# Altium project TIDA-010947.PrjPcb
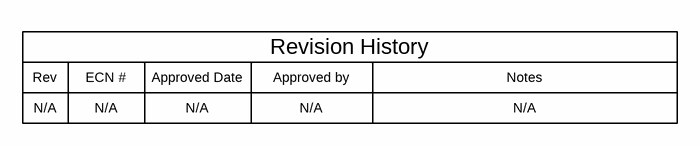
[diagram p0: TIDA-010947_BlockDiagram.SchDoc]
CopyrightYear: 2024; PCB_Layout: Who did the Layout?; PCB_Rev: E1.2; PRJ_Customer: Public Release; PRJ_Engineer: Enter name of project lead; PRJ_Number: TIDA-010947; PRJ_Title: Change in menu Project|Project Options|Parameters; SCH_Rev: E1.2; TechSupport: http://www.ti.com/support; TID: N/A
3 sheets, 68 parts. Net scope: flat (ports and power ports of the same name join across sheets).
Board file: TIDA-010947_PCB_E1.2.PcbDoc
Sheets:
  TIDA-010947_BlockDiagram.SchDoc
  TIDA-010947_Schematic.SchDoc
  TIDA-010947_Hardware.SchDoc

## Sheet TIDA-010947_BlockDiagram.SchDoc
size 431 x 279 mm; Date: Not shown in title block; ApprovedBy: Not shown in title block; CheckedBy: Not shown in title block; Author: Not shown in title block; CompanyName: Not shown in title block; Engineer: Not shown in title block; Organization: Not shown in title block; Address1: Not shown in title block; Address2: Not shown in title block; Address3: Not shown in title block; Address4: Not shown in title block; DocumentNumber: 1; Revision: Use project parameter SCH_Rev; SheetNumber: 1; SheetTotal: 3; PageSetup: Record=PageOptions¦CenterHorizontal=True¦CenterVertical=True¦PrintScale=1.00¦XCorrection=1.00¦YCorrection=1.00¦PrintKind=0¦BorderSize=5000000¦LeftOffset=0¦BottomOffset=0¦Orientation=2¦PaperLength=1000¦PaperWidth=1000¦Scale=100¦PaperSource=15¦PrintQuality=600¦MediaType=1¦DitherType=10¦PaperKind=Letter¦PrintScaleMode=1

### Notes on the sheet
- Rev
- N/A
- ECN #
- Approved Date
- Approved by
- Revision History
- Notes

## Sheet TIDA-010947_Schematic.SchDoc
size 431 x 279 mm; Date: Not shown in title block; ApprovedBy: Not shown in title block; CheckedBy: Not shown in title block; Author: Not shown in title block; CompanyName: Not shown in title block; Engineer: Not shown in title block; Organization: Not shown in title block; Address1: Not shown in title block; Address2: Not shown in title block; Address3: Not shown in title block; Address4: Not shown in title block; DocumentNumber: 2; Revision: Use project parameter SCH_Rev; SheetNumber: 2; SheetTotal: 3; PageSetup: Record=PageOptions¦CenterHorizontal=True¦CenterVertical=True¦PrintScale=1.00¦XCorrection=1.00¦YCorrection=1.00¦PrintKind=0¦BorderSize=5000000¦LeftOffset=0¦BottomOffset=0¦Orientation=2¦PaperLength=1000¦PaperWidth=1000¦Scale=100¦PaperSource=15¦PrintQuality=600¦MediaType=1¦DitherType=10¦PaperKind=Letter¦PrintScaleMode=1
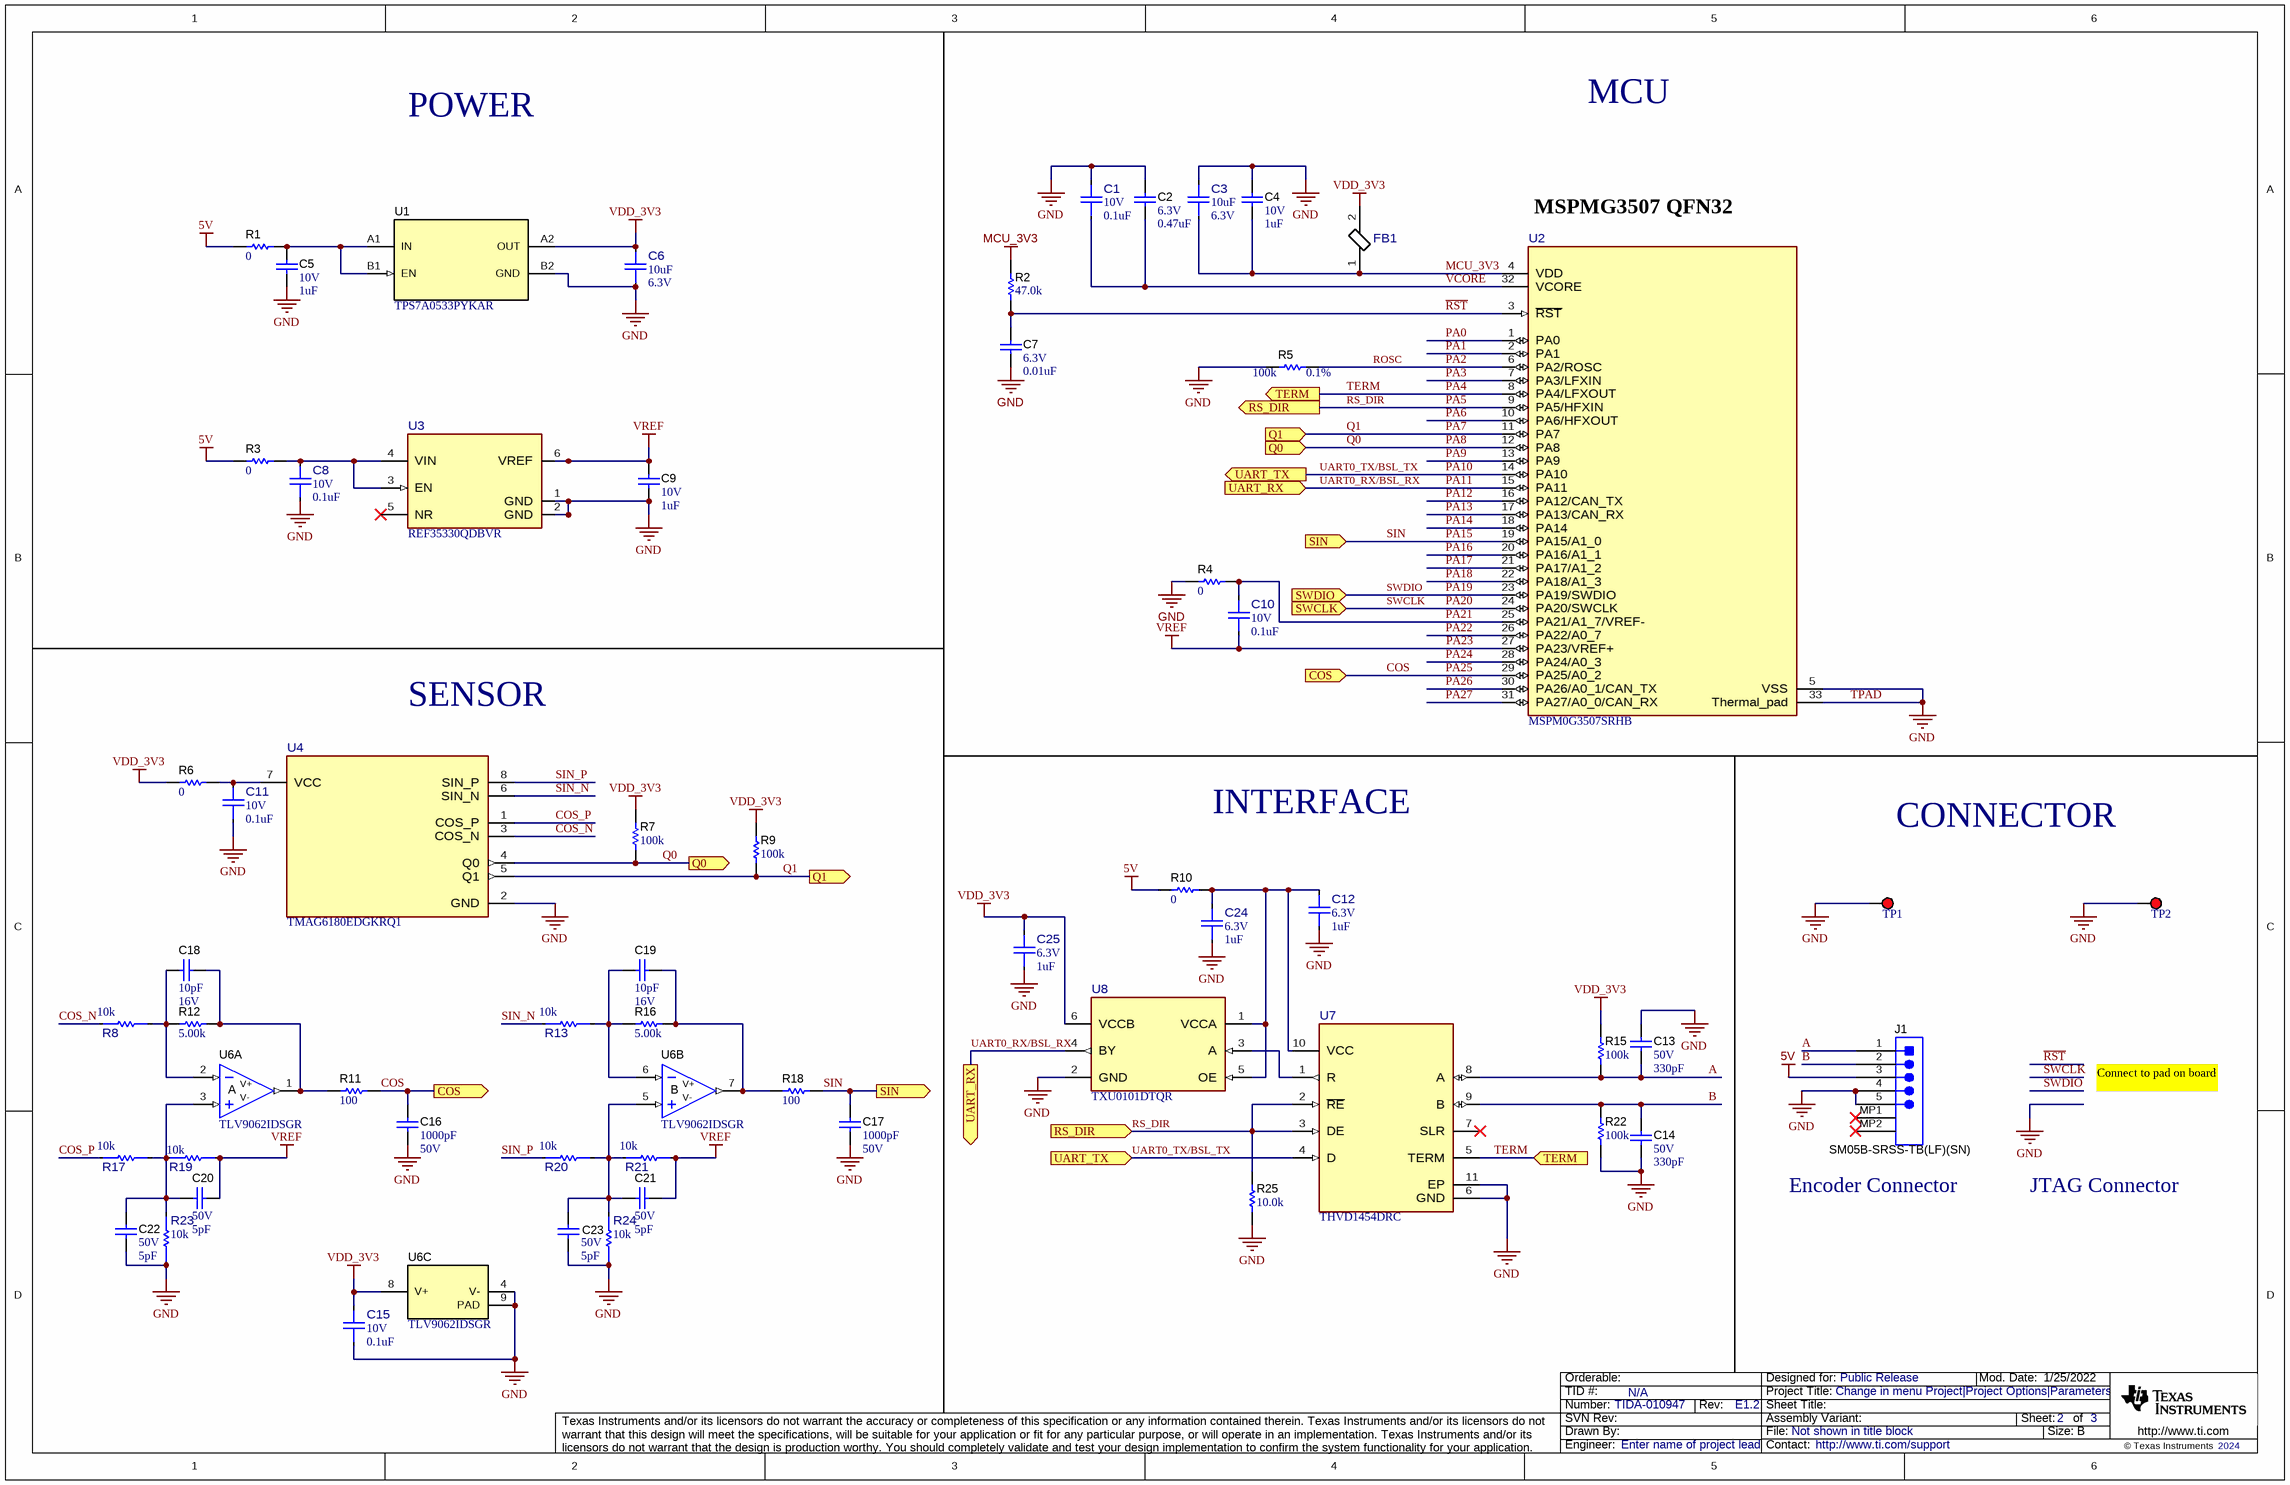
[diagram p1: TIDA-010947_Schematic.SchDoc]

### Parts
C1  VDC_V: 10V  ValueDisplayed: 0.1uF  [FP-LMK063BJ104KP-F_0201-MFG]  (hidden comment: LMK063BJ104KP-F)
C2  VDC_V: 6.3V  ValueDisplayed: 0.47uF  [0201_033]  (hidden comment: CL03A474KQ3NNNC)
C3  ValueDisplayed: 10uF  VDC_V: 6.3V  [FP-ZRB15XC80J106ME05D_0402-MFG]  (hidden comment: ZRB15XC80J106ME05D)
C4  VDC_V: 10V  ValueDisplayed: 1uF  [0201]  (hidden comment: CL03A105MP3NSNC)
C5  VDC_V: 10V  ValueDisplayed: 1uF  [0201]  (hidden comment: CL03A105MP3NSNC)
C6  ValueDisplayed: 10uF  VDC_V: 6.3V  [FP-ZRB15XC80J106ME05D_0402-MFG]  (hidden comment: ZRB15XC80J106ME05D)
C7  VDC_V: 6.3V  ValueDisplayed: 0.01uF  [0201]  (hidden comment: GRM033R60J103KA01D)
C8  VDC_V: 10V  ValueDisplayed: 0.1uF  [FP-LMK063BJ104KP-F_0201-MFG]  (hidden comment: LMK063BJ104KP-F)
C9  VDC_V: 10V  ValueDisplayed: 1uF  [0201]  (hidden comment: CL03A105MP3NSNC)
C10  VDC_V: 10V  ValueDisplayed: 0.1uF  [FP-LMK063BJ104KP-F_0201-MFG]  (hidden comment: LMK063BJ104KP-F)
C11  VDC_V: 10V  ValueDisplayed: 0.1uF  [FP-LMK063BJ104KP-F_0201-MFG]  (hidden comment: LMK063BJ104KP-F)
C12  VDC_V: 6.3V  ValueDisplayed: 1uF  [FP-JMK063BC6105MP-F_0201-MFG]  (hidden comment: JMK063BC6105MP-F)
C13  VDC_V: 50V  ValueDisplayed: 330pF  [0201_033]  (hidden comment: CGA1A2X7R1H331K030BA)
C14  VDC_V: 50V  ValueDisplayed: 330pF  [0201_033]  (hidden comment: CGA1A2X7R1H331K030BA)
C15  VDC_V: 10V  ValueDisplayed: 0.1uF  [FP-LMK063BJ104KP-F_0201-MFG]  (hidden comment: LMK063BJ104KP-F)
C16  ValueDisplayed: 1000pF  VDC_V: 50V  [0402]  (hidden comment: CGA2B2X8R1H102K050BA)
C17  ValueDisplayed: 1000pF  VDC_V: 50V  [0402]  (hidden comment: CGA2B2X8R1H102K050BA)
C18  Cap_F: 10pF  VDC_V: 16V  [0402]  (hidden comment: C0402C100K4GACTU)
C19  Cap_F: 10pF  VDC_V: 16V  [0402]  (hidden comment: C0402C100K4GACTU)
C20  VDC_V: 50V  ValueDisplayed: 5pF  [0402]  (hidden comment: GRM1555C1H5R0CA01D)
C21  VDC_V: 50V  ValueDisplayed: 5pF  [0402]  (hidden comment: GRM1555C1H5R0CA01D)
C22  VDC_V: 50V  ValueDisplayed: 5pF  [0402]  (hidden comment: GRM1555C1H5R0CA01D)
C23  VDC_V: 50V  ValueDisplayed: 5pF  [0402]  (hidden comment: GRM1555C1H5R0CA01D)
C24  VDC_V: 6.3V  ValueDisplayed: 1uF  [FP-JMK063BC6105MP-F_0201-MFG]  (hidden comment: JMK063BC6105MP-F)
C25  VDC_V: 6.3V  ValueDisplayed: 1uF  [FP-JMK063BC6105MP-F_0201-MFG]  (hidden comment: JMK063BC6105MP-F)
FB1  MPZ1005S121HT000  [FP-MPZ1005S121HT000_0402-MFG]  (value not drawn)
J1  SM05B-SRSS-TB(LF)(SN)  [JST_SM05B-SRSS-TB]
R1  ValueDisplayed: 0  [0402]  (hidden comment: RC0402JR-070RL)
R2  ValueDisplayed: 47.0k  [0201]  (hidden comment: RK73H1HTTC4702F)
R3  ValueDisplayed: 0  [0402]  (hidden comment: RC0402JR-070RL)
R4  ValueDisplayed: 0  [0201]  (hidden comment: ERJ-1GN0R00C)
R5  Value1: 0.1%  ValueDisplayed: 100k  [0402]  (hidden comment: RG1005P-104-B-T5)
R6  ValueDisplayed: 0  [0402]  (hidden comment: RC0402JR-070RL)
R7  ValueDisplayed: 100k  [0201]  (hidden comment: RC0201DR-07100KL)
R8  value 10k  [FP-RT0402BRB0710KL_0402-MFG]  (hidden comment: RT0402BRB0710KL)
R9  ValueDisplayed: 100k  [0201]  (hidden comment: RC0201DR-07100KL)
R10  ValueDisplayed: 0  [0402]  (hidden comment: RC0402JR-070RL)
R11  ValueDisplayed: 100  [0402]  (hidden comment: RMCF0402JT100R)
R12  ValueDisplayed: 5.00k  [0402]  (hidden comment: PNM0402E5001BST1)
R13  value 10k  [FP-RT0402BRB0710KL_0402-MFG]  (hidden comment: RT0402BRB0710KL)
R15  ValueDisplayed: 100k  [0201]  (hidden comment: RC0201DR-07100KL)
R16  ValueDisplayed: 5.00k  [0402]  (hidden comment: PNM0402E5001BST1)
R17  value 10k  [FP-RT0402BRB0710KL_0402-MFG]  (hidden comment: RT0402BRB0710KL)
R18  ValueDisplayed: 100  [0402]  (hidden comment: RMCF0402JT100R)
R19  value 10k  [FP-RT0402BRB0710KL_0402-MFG]  (hidden comment: RT0402BRB0710KL)
R20  value 10k  [FP-RT0402BRB0710KL_0402-MFG]  (hidden comment: RT0402BRB0710KL)
R21  value 10k  [FP-RT0402BRB0710KL_0402-MFG]  (hidden comment: RT0402BRB0710KL)
R22  ValueDisplayed: 100k  [0201]  (hidden comment: RC0201DR-07100KL)
R23  value 10k  [FP-RT0402BRB0710KL_0402-MFG]  (hidden comment: RT0402BRB0710KL)
R24  value 10k  [FP-RT0402BRB0710KL_0402-MFG]  (hidden comment: RT0402BRB0710KL)
R25  ValueDisplayed: 10.0k  [0201]  (hidden comment: RC0201DR-0710KL)
TP1  5000  [Keystone5000]  (value not drawn)
TP2  5000  [Keystone5000]  (value not drawn)
U1  TPS7A0533PYKAR  [YKA0004AAAA]
U2  MSPM0G3507SRHB  [RHB0032E-MFG]
U3  REF35330QDBVR  [DBV0006A-MFG]
U4  TMAG6180EDGKRQ1  [DGK0008A-MFG]
U6  TLV9062IDSGR  [DSG0008A]  (parts A,B,C of 3)
U7  THVD1454DRC  [DRC0010J-MFG]
U8  TXU0101DTQR  [DTQ0006A-MFG]

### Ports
COS (in), COS (out), Q0 (in), Q0 (out), Q1 (in), Q1 (out), RS_DIR (in), RS_DIR (out), SIN (in), SIN (out), SWCLK (in), SWDIO (in), TERM (in), TERM (out), UART_RX (in), UART_RX (out), UART_TX (in), UART_TX (out)

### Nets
5V: J1.3 R1.1 R3.1 R10.1
MCU_3V3: C3.1 C4.2 FB1.1 R2.2 U2.4(VDD)
PA23: C9.1 C10.1 C20.1 C21.1 R19.2 R21.2 U2.27(PA23/VREF+) U3.6(VREF)  [also labelled VREF]
TPAD: C1.2 C2.1 C3.2 C4.1 C5.2 C6.1 C7.2 C8.1 C9.2 C11.1 C12.1 C13.1 C14.2 C15.1 C16.2 C17.2 C22.2 C23.2 C24.1 C25.1 J1.4 J1.5 R4.1 R5.1 R22.1 R23.1 R24.1 R25.1 TP1.1 TP2.1 U1.B2(GND) U2.5(VSS) U2.33(Thermal_pad) U3.1(GND) U3.2(GND) U4.2(GND) U6.4(V-) U6.9(PAD) U7.6(GND) U7.11(EP) U8.2(GND)  [also labelled GND]
VDD_3V3: C6.2 C15.2 C25.2 FB1.2 R6.1 R7.2 R9.2 R15.2 U1.A2(OUT) U6.8(V+) U8.6(VCCB)
A: C13.2 J1.1 R15.1 U7.8(A)
B: C14.1 J1.2 R22.2 U7.9(B)
COS: C16.1 R11.2 U2.29(PA25/A0_2) ; port COS  [also labelled PA25]
COS_N: R8.1 U4.3(COS_N)
COS_P: R17.1 U4.1(COS_P)
PA0: U2.1(PA0)
PA1: U2.2(PA1)
PA2: R5.2 U2.6(PA2/ROSC)  [also labelled ROSC]
PA3: U2.7(PA3/LFXIN)
PA4: U2.8(PA4/LFXOUT) U7.5(TERM) ; port TERM  [also labelled TERM]
PA5: R25.2 U2.9(PA5/HFXIN) U7.2(~{RE}) U7.3(DE) ; port RS_DIR  [also labelled RS_DIR]
PA6: U2.10(PA6/HFXOUT)
PA7: R9.1 U2.11(PA7) U4.5(Q1) ; port Q1  [also labelled Q1]
PA8: R7.1 U2.12(PA8) U4.4(Q0) ; port Q0  [also labelled Q0]
PA9: U2.13(PA9)
PA10: U2.14(PA10) U7.4(D) ; port UART_TX  [also labelled UART0_TX/BSL_TX]
PA11: U2.15(PA11) U8.4(BY) ; port UART_RX  [also labelled UART0_RX/BSL_RX]
PA12: U2.16(PA12/CAN_TX)
PA13: U2.17(PA13/CAN_RX)
PA14: U2.18(PA14)
PA15: C17.1 R18.2 U2.19(PA15/A1_0) ; port SIN  [also labelled SIN]
PA16: U2.20(PA16/A1_1)
PA17: U2.21(PA17/A1_2)
PA18: U2.22(PA18/A1_3)
PA19: U2.23(PA19/SWDIO) ; port SWDIO  [also labelled SWDIO]
PA20: U2.24(PA20/SWCLK) ; port SWCLK  [also labelled SWCLK]
PA21: C10.2 R4.2 U2.25(PA21/A1_7/VREF-)
PA22: U2.26(PA22/A0_7)
PA24: U2.28(PA24/A0_3)
PA26: U2.30(PA26/A0_1/CAN_TX)
PA27: U2.31(PA27/A0_0/CAN_RX)
~{RST}: C7.1 R2.1 U2.3(~{RST})
SIN_N: R13.1 U4.6(SIN_N)
SIN_P: R20.1 U4.8(SIN_P)
VCORE: C1.1 C2.2 U2.32(VCORE)
NetC5_1: C5.1 R1.2 U1.A1(IN) U1.B1(EN)
NetC8_2: C8.2 R3.2 U3.3(EN) U3.4(VIN)
NetC11_2: C11.2 R6.2 U4.7(VCC)
NetC12_2: C12.2 C24.2 R10.2 U7.10(VCC) U8.1(VCCA) U8.5(OE)
NetC18_1: C18.1 R11.1 R12.2 U6.1(OUT)
NetC18_2: C18.2 R8.2 R12.1 U6.2(IN-)
NetC19_1: C19.1 R16.2 R18.1 U6.7(OUT)
NetC19_2: C19.2 R13.2 R16.1 U6.6(IN-)
NetC20_2: C20.2 C22.1 R17.2 R19.1 R23.2 U6.3(IN+)
NetC21_2: C21.2 C23.1 R20.2 R21.1 R24.2 U6.5(IN+)
NetU7_1: U7.1(R) U8.3(A)

Not connected (* = marked no-connect by the designer): J1 MP1* MP2*; U3 5(NR)*; U7 7(SLR)*

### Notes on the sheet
- POWER
- MCU
- MSPMG3507 QFN32
- SENSOR
- INTERFACE
- CONNECTOR
- Connect to pad on board
- (near J1) Encoder Connector
- JTAG Connector

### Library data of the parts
C1 C8 C10 C11 C15 = CMP-0092661-1: CAP CER 0.1UF 10V X5R 0201; Manufacturer: Taiyo Yuden; AEC Qualified: No; Value: 100nF; Tolerance_%: 10%; SizeZ_mm: 0.33mm; TempCo: 15%
C2 = CMP-0009658-2: CAP, CERM, 0.47 uF, 6.3 V, +/- 10%, X5R, 0201; Manufacturer: Samsung Electro-Mechanics; TaMin_C: -55°C; Polarized: N; SizeAreaWB_mm2: 2.08; Value1: Unknown; U/M: EA; Value: 0.47uF; TaMax_C: 85°C; SizeZ_mm: 0.33; SizeX_mm: 0.6; SizeY_mm: 0.3; Cap_Case: 0201; SizeArea_mm2: 0.18; Cap_F: 470nF; AEC Category: Q200
C3 C6 = CMP-0035038-1: 10µF ±20% 6.3V Ceramic Capacitor X6S 0402 (1005 Metric); Manufacturer: Murata; AEC Qualified: No; SizeZ_mm: 0.85mm; TempCo: 22%
C4 C5 C9 = CMP-0009656-3: CAP, CERM, 1 uF, 10 V, +/- 20%, X5R, 0201; Manufacturer: Samsung Electro-Mechanics; TaMin_C: -55°C; Polarized: N; SizeAreaWB_mm2: 2.08; Value1: Unknown; U/M: EA; Value: 1uF; TaMax_C: 85°C; SizeZ_mm: 0.26; SizeX_mm: 0.6; SizeY_mm: 0.3; SizeArea_mm2: 0.18; Cap_F: 1µF; AEC Category: Q200
C7 = CMP-0009689-1: CAP, CERM, 0.01 uF, 6.3 V, +/- 10%, X5R, 0201; Manufacturer: MuRata; TaMin_C: -55°C; Polarized: N; SizeAreaWB_mm2: 2.08; Value1: Unknown; U/M: EA; Value: 0.01uF; TaMax_C: 85°C; SizeZ_mm: 0.26; SizeX_mm: 0.6; SizeY_mm: 0.3; SizeArea_mm2: 0.18; Cap_F: 10nF; AEC Category: Q200
C12 C24 C25 = CMP-0089441-1: 1µF ±20% 6.3V Ceramic Capacitor X6S 0201 (0603 Metric); Manufacturer: Taiyo Yuden; AEC Qualified: No; TempCo: 22%; SizeZ_mm: 0.39mm
C13 C14 = CMP-0009653-3: CAP, CERM, 330 pF, 50 V, +/- 10%, X7R, AEC-Q200 Grade 1, 0201; Manufacturer: TDK; TaMin_C: -55°C; ESR_ohm: 8.053; Polarized: N; SizeAreaWB_mm2: 2.08; Value1: 8.05302 ohm; U/M: EA; Value: 330pF; TaMax_C: 125°C; SizeZ_mm: 0.33; SizeX_mm: 0.6; SizeY_mm: 0.3; SizeArea_mm2: 0.18; AEC Qualified: Y; IRMS_A: 210.618mA; AEC Grade: 1; AEC Category: Q200
C16 C17 = CMP-0860997-1: CAP, CERM, 1000 pF, 50 V,+/- 10%, X8R, AEC-Q200 Grade 0, 0402; Manufacturer: TDK; SizeArea_mm2: 0.5; U/M: EA; SizeX_mm: 1; Polarized: N; AEC Grade: 0; AEC Qualified: Y; TaMin_C: -55°C; Value: 1000pF; TaMax_C: 150°C; SizeZ_mm: 0.6; Cap_F: 1nF; SizeAreaWB_mm2: 3; AEC Category: Q200
C18 C19 = CMP-0079539-1: CAP, CERM, 10 pF, 16 V,+/- 10%, C0G, 0402; Manufacturer: Kemet; SizeAreaWB_mm2: 3; SizeArea_mm2: 0.5; AEC Qualified: N; AEC Category: Q200; Value: 10pF; TaMax_C: 125°C; SizeZ_mm: 0.6; Green_REACh: Passed; TaMin_C: -55°C; Green_Lifecycle: Active; U/M: EA; SizeX_mm: 1
C20-C23 = CMP-0006480-1: CAP, CERM, 5 pF, 50 V, +/- 5%, C0G/NP0, 0402; Manufacturer: MuRata; TaMin_C: -55°C; Polarized: N; SizeAreaWB_mm2: 3; Value1: Unknown; U/M: EA; Value: 5pF; TaMax_C: 125°C; SizeZ_mm: 0.6; SizeX_mm: 1; SizeY_mm: 0.5; AEC Category: Q200
FB1 = CMP-0087087-1: FERRITE BEAD 120 OHM 0402 1LN; Manufacturer: TDK; Symbol Name: SYM-MPZ1005S121HT000; Imax_A: 2A; DCR_ohm: 55mΩ; SizeZ_mm: 0.55mm
J1 = CMP-0079869-1: Header (Shrouded), 1 mm, 5x1, Tin, R/A, SMT; Manufacturer: JST Manufacturing; Pitch_mm: 1; Gender: Male; Cert_CSA: Y; Voltage_V: 50V; Current_A: 700mA
R1 R3 R6 R10 = CMP-0027004-1: RES, 0, 5%, 0.063 W, 0402; Manufacturer: Yageo America; Power_W: 63mW; TempCo: 200 ppm/C; Value_Code: 0000; U/M: EA; Value: 0; EIA_Code: E24; SizeX_mm: 1; SizeY_mm: 0.5; SizeZ_mm: 0.6; Value2: 0.063W; VDC_V: 50V; AEC Category: Q200
R2 = CMP-0028126-1: RES, 47.0 k, 1%, 0.05 W, AEC-Q200 Grade 0, 0201; Manufacturer: KOA Speer; Power_W: 50mW; TempCo: 200 ppm/C; Value_Code: 47k0; U/M: EA; Value: 47.0k; Res_ohm: 47k; SizeX_mm: 0.6; SizeY_mm: 0.3; SizeZ_mm: 0.26; Value2: 0.05W; SizeArea_mm2: 0.18; AEC Qualified: Y; VDC_V: 25V; AEC Grade: 0; AEC Category: Q200
R4 = CMP-0065361-1: RES, 0, 5%, .05 W, AEC-Q200 Grade 0, 0201; Manufacturer: Panasonic; Power_W: 50mW; Green_Lifecycle: Not Set; TempCo: ppm/C; Value_Code: 0000; Green_REACh: Incomplete; U/M: EA; Value: 0; EIA_Code: E24; SizeX_mm: 0.6; SizeY_mm: 0.3; SizeZ_mm: 0.26; Value2: .05W; SizeArea_mm2: 0.18; AEC Qualified: Y; AEC Category: Q200
R5 = CMP-0026815-1: RES, 100 k, 0.1%, 0.063 W, 0402; Manufacturer: Susumu Co Ltd; Power_W: 63mW; TempCo: 25 ppm/C; U/M: EA; Value: 100k; EIA_Code: E192; SizeX_mm: 1; SizeY_mm: 0.5; SizeZ_mm: 0.6; Value2: 0.063W; AEC Category: Q200
R7 R9 R15 R22 = CMP-0028132-1: RES, 100 k, 0.5%, 0.05 W, 0201; Manufacturer: Yageo America; Power_W: 50mW; TempCo: 200 ppm/C; U/M: EA; Value: 100k; EIA_Code: E192; SizeX_mm: 0.6; SizeY_mm: 0.3; SizeZ_mm: 0.26; Value2: 0.05W; SizeArea_mm2: 0.18; AEC Qualified: N; VDC_V: 25V; AEC Category: Q200
R8 R13 R17 R19-R21 R23 R24 = CMP-0121803-1: 10 kOhms ±0.1% 0.063W, 1/16W Chip Resistor 0402 (1005 Metric) Thin Film; Manufacturer: Yageo; AEC Qualified: No; Power_W: 63mW; SizeZ_mm: 0.35mm; TempCo: 10ppm/°C; VDC_V: 50V
R11 R18 = CMP-0026763-1: RES, 100, 1%, 0.063 W, AEC-Q200 Grade 0, 0402; Manufacturer: Stackpole Electronics Inc; Power_W: 63mW; TempCo: 100 ppm/C; Value_Code: 100R; U/M: EA; Value: 100; EIA_Code: E96; SizeX_mm: 1; SizeY_mm: 0.5; SizeZ_mm: 0.6; Value2: 0.063W; AEC Qualified: Y; AEC Grade: 0; AEC Category: Q200
R12 R16 = CMP-0026813-1: RES, 5.00 k, 0.1%, 0.05 W, 0402; Manufacturer: Vishay-Dale; Power_W: 50mW; TempCo: 25 ppm/C; Value_Code: 5k00; U/M: EA; Value: 5.00k; Res_ohm: 5k; SizeX_mm: 1; SizeY_mm: 0.5; SizeZ_mm: 0.6; Value2: 0.05W; AEC Qualified: N; VDC_V: 75V; AEC Category: Q200
R25 = CMP-0028133-1: RES, 10.0 k, 0.5%, 0.05 W, 0201; Manufacturer: Yageo America; Power_W: 50mW; TempCo: 200 ppm/C; Value_Code: 10k0; U/M: EA; Value: 10.0k; EIA_Code: E192; Res_ohm: 10k; SizeX_mm: 0.6; SizeY_mm: 0.3; SizeZ_mm: 0.26; Value2: 0.05W; SizeArea_mm2: 0.18; AEC Qualified: N; VDC_V: 25V; AEC Category: Q200
TP1 TP2 = CMP-0055137-1: Test Point, Miniature, Red, TH; Manufacturer: Keystone; CNHeader: FALSE; Green_Lifecycle: Active; Green_REACh: Passed; ContactFinish: Silver; CT: TRUE
U1 = CMP-0086328-1: 1µA, ultra-low Iq, 200mA low-dropout (LDO) regulator in a small-size package, YKA0004AAAA (DSBGA-4); Manufacturer: Texas Instruments; AEC Category: Q200; SizeX_mm: 0.7; AEC Qualified: N; SizeZ_mm: 0.4; SizeAreaWB_mm2: 2.89; Rating: Catalog; CompType: IC; SizeArea_mm2: 0.49
U2 = CMP-0093963-1: Mixed-Signal Microcontrollers with CAN-FD Interface, VQFN32; Manufacturer: Texas Instruments; TaMin_C: -40°C; Interface: I2C,SPI,UART,CAN,LIN,IrDA,SMBus; Number Of Cores: 1; Number Of Pwm Channels: 16; Data Bus Width: 32bits; Frequency_Fixed: 80MHz; Core Architecture: ARM Cortex-M0+; Number Of Timers/Counters: 7; Number Of Adc Channels: 10; Number Of Uart Channels: 4; Standoff Height: 0mm; Ram Size: 32KBytes; Number Of A/D Converters: 2; SizeZ_mm: 1mm; AEC Qualified: No; TaMax_C: +125°C; Memory Size: 128KBytes; TJmax_C: +130°C; Min Supply Voltage: 1.62V; Max Supply Voltage: 3.6V; Memory Type: FLASH; Number Of I/Os: 28
U3 = CMP-0122722-1: 650-nA quiescent current, 12-ppm/°C drift, ultra-low-power precision voltage reference 6-SOT-23 -40 to 125; Manufacturer: Texas Instruments; SizeZ_mm: 1.45mm; AEC Qualified: No; Max Supply Voltage: 6V; Min Supply Voltage: 3.55V; Nominal Supply Current: 0.65uA; Number Of Outputs: 1; Output Type: Fixed; Output Voltage: 3.3V; Reference Type: Series; Standoff Height: 0mm; TaMax_C: +125°C; TaMin_C: -40°C
U4 = CMP-0095386-1: Hall Effect Magnetic Sensor VSSOP8; Manufacturer: Texas Instruments; SizeZ_mm: 1.1mm; Standoff Height: 0.05mm; AEC Grade: Grade 0; Max Supply Voltage: 5.5V; Min Supply Voltage: 2.7V; AEC Qualified: Yes
U6 = CMP-0077462-2: 10-MHz, Low-Noise, RRIO, CMOS Operational Amplifier for Cost-Sensitive Systems, DSG0008A (WSON-8); Manufacturer: Texas Instruments; Alternate PartNumber: TLV9062IDSGT; SizeAreaWB_mm2: 9.0; SizeArea_mm2: 4.0; AEC Qualified: N; AEC Category: Q200; SizeZ_mm: 0.8; SizeY_mm: 2.0; CompType: IC; Rating: Catalog
U7 = CMP-0094703-1: Manufacturer: Texas Instruments; Standoff Height: 0mm; SizeZ_mm: 1mm; AEC Qualified: Unknown
U8 = CMP-0065573-1: Single-Bit Fixed Direction Voltage-Level Translator with Schmitt-Trigger Inputs and 3-State Outputs; Manufacturer: Texas Instruments; SizeZ_mm: 0.4mm; AEC Qualified: No; Data Rate: 200Mbits/s; Logic Function Desc: Non-Inverting; Nominal Supply Current: 2.5uA; Number Of Inputs: 1; Propagation Delay: 8ns; Standoff Height: 0mm; TaMax_C: +125°C; TaMin_C: -40°C; TJmax_C: +150°C; V A Max: 5.5V; V A Min: 1.08V

## Sheet TIDA-010947_Hardware.SchDoc
size 431 x 279 mm; Date: Not shown in title block; ApprovedBy: Not shown in title block; CheckedBy: Not shown in title block; Author: Not shown in title block; CompanyName: Not shown in title block; Engineer: Not shown in title block; Organization: Not shown in title block; Address1: Not shown in title block; Address2: Not shown in title block; Address3: Not shown in title block; Address4: Not shown in title block; DocumentNumber: 3; Revision: Use project parameter SCH_Rev; SheetNumber: 3; SheetTotal: 3; PageSetup: Record=PageOptions¦CenterHorizontal=True¦CenterVertical=True¦PrintScale=1.00¦XCorrection=1.00¦YCorrection=1.00¦PrintKind=0¦BorderSize=5000000¦LeftOffset=0¦BottomOffset=0¦Orientation=2¦PaperLength=1000¦PaperWidth=1000¦Scale=100¦PaperSource=15¦PrintQuality=600¦MediaType=1¦DitherType=10¦PaperKind=Letter¦PrintScaleMode=1
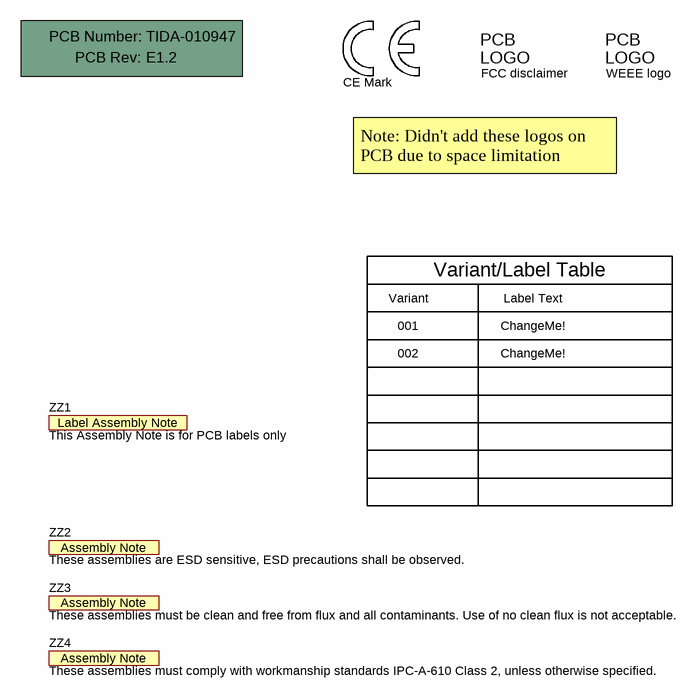
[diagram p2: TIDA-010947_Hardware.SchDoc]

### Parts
!PCB  Printed Circuit Board  (value not drawn)  (mechanical)
LOGO1  FCC disclaimer  [FCC_disclaimer]  (no BOM)
Logo2  WEEE logo  [WEEE_Minimum]  (no BOM)
Logo3  CE Mark  [CE_Mark_5mm]  (no BOM)
ZZ1  This Assembly Note is for PCB labels only  [AssemblyNoteLabel]  (no BOM)
ZZ2  These assemblies are ESD sensitive, ESD precautions shall be observed.  [AssemblyNote]  (no BOM)
ZZ3  These assemblies must be clean and free from flux and all contaminants. Use of no clean flux is not acceptable.  [AssemblyNote]  (no BOM)
ZZ4  These assemblies must comply with workmanship standards IPC-A-610 Class 2, unless otherwise specified.  [AssemblyNote]  (no BOM)

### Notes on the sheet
- Note: Didn't add these logos on PCB due to space limitation
- Variant
- Variant/Label Table
- Label Text
- 001
- 002
- ChangeMe!

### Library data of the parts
!PCB = CMP-0003618-2: Manufacturer: Any; PartNumber: TIDA-010947
LOGO1 = CMP-0074847-1: FCC_disclaimer; Library Reference: Logo
Logo2 = CMP-0074769-1
Logo3 = CMP-0074844-1: SymbolCreator: a0412235
ZZ1 = CMP-0003616-3
ZZ2 = CMP-0077236-1
ZZ3 = CMP-0077237-1
ZZ4 = CMP-0077238-1

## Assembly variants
001: not fitted FID1 FID2 FID3 J2 J2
